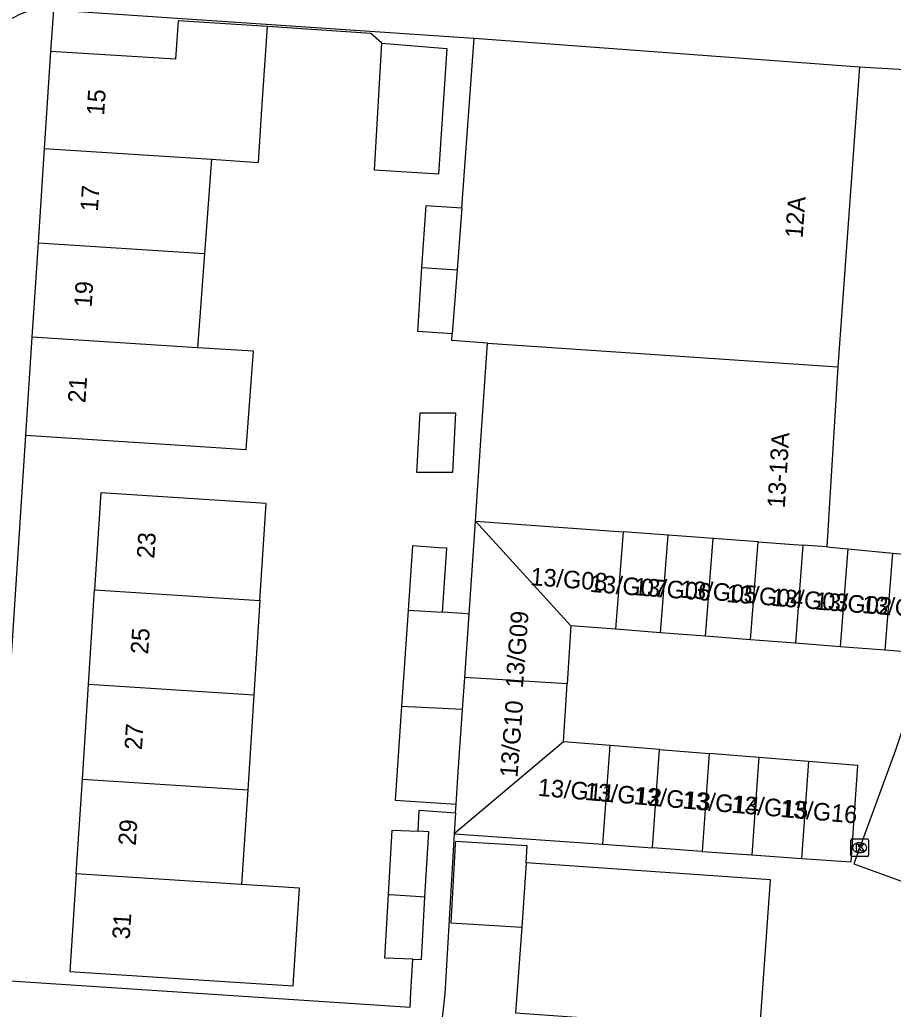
# Model space of a CAD drawing. Extents: x 160356 to 161355, y 381727 to 382845.
# Drawn here: x 160572.4 to 160622.2, y 382168.2 to 382224.6 of the extents above; entities that cross this region are included whole.
import ezdxf

# ---------------------------------------------------------------- set-up
doc = ezdxf.new("R2010")
doc.units = 0
for name, color, linetype in [('IMGEO_Kolk', 7, 'Continuous'), ('IMGEO_Muur', 7, 'Continuous'), ('IMGEO_Pand', 7, 'Continuous'), ('IMGEO_Pand_nummerreeks', 7, 'Continuous'), ('IMGEO_Rijbaan_lokaal_open', 7, 'Continuous'), ('IMGEO_Voetpad_open', 7, 'Continuous')]:
    doc.layers.add(name, color=color, linetype=linetype)

msp = doc.modelspace()

# ---------------------------------------------------------------- linework, layer by layer
at = {"layer": 'IMGEO_Kolk'}
for p, q in [((160619.77, 382176.998), (160619.77, 382177.85)), ((160619.845, 382177.924), (160620.697, 382177.924)), ((160620.258, 382177.704), (160620.283, 382177.704)), ((160620.771, 382177.85), (160620.771, 382176.998)), ((160620.697, 382176.924), (160619.845, 382176.924)), ((160620.281, 382177.144), (160620.256, 382177.144))]:
    msp.add_line(p, q, dxfattribs=at)
for points in [[(160619.77, 382176.998), (160619.77, 382177.85)], [(160619.845, 382177.924), (160620.697, 382177.924)], [(160620.091, 382177.624), (160620.214, 382177.624), (160620.214, 382177.473), (160620.344, 382177.624), (160620.508, 382177.624), (160620.362, 382177.473), (160620.515, 382177.224), (160620.363, 382177.224), (160620.278, 382177.388), (160620.214, 382177.321), (160620.214, 382177.224), (160620.091, 382177.224), (160620.091, 382177.624)], [(160620.771, 382177.85), (160620.771, 382176.998)], [(160620.697, 382176.924), (160619.845, 382176.924)]]:
    msp.add_lwpolyline(points, dxfattribs=at)
for centre, start, end in [((160619.847, 382177.848), 91.552, 178.448), ((160619.847, 382177.848), 91.552, 178.448), ((160620.695, 382177.848), 1.552, 88.448), ((160620.695, 382177.848), 1.552, 88.448), ((160619.847, 382177), 181.552, 268.448), ((160619.847, 382177), 181.552, 268.448), ((160620.695, 382177), 271.552, 358.448), ((160620.695, 382177), 271.552, 358.448)]:
    msp.add_arc(centre, 0.0765, start, end, dxfattribs=at)
for centre, major_axis, ratio, start_param, end_param in [((160620.257, 382177.424), (-0.387, 0.002), 0.722429, 4.712389, 7.853982), ((160620.282, 382177.424), (-0.39, 0.002), 0.717154, 1.570796, 4.712389)]:
    msp.add_ellipse(centre, major_axis=major_axis, ratio=ratio, start_param=start_param, end_param=end_param, dxfattribs=at)
at = {"layer": 'IMGEO_Muur'}
msp.add_lwpolyline([(160593.062, 382223.233), (160592.435, 382223.786), (160586.548, 382224.183)], dxfattribs=at)
at = {"layer": 'IMGEO_Pand'}
for points in [[(160583.35, 382216.629), (160586.024, 382216.454), (160586.21, 382219.195), (160586.548, 382224.183), (160581.462, 382224.509), (160581.314, 382222.32), (160574.19, 382222.775)], [(160592.644, 382216.014), (160593.062, 382223.233), (160596.757, 382222.942), (160596.275, 382215.777), (160592.644, 382216.014)], [(160597.604, 382213.868), (160598.324, 382223.525)], [(160598.324, 382223.525), (160620.253, 382221.901)], [(160574.19, 382222.775), (160573.829, 382217.237)], [(160620.253, 382221.901), (160619.027, 382204.801)], [(160573.829, 382217.237), (160573.479, 382211.868)], [(160573.829, 382217.237), (160583.35, 382216.629)], [(160583.35, 382216.629), (160582.958, 382211.262)], [(160595.343, 382210.47), (160595.58, 382214.004), (160597.604, 382213.868)], [(160597.604, 382213.868), (160597.341, 382210.342)], [(160573.479, 382211.868), (160573.129, 382206.49)], [(160573.479, 382211.868), (160582.958, 382211.262)], [(160582.958, 382211.262), (160582.695, 382207.663), (160582.565, 382205.893)], [(160597.069, 382206.696), (160595.098, 382206.829), (160595.343, 382210.47)], [(160595.343, 382210.47), (160597.341, 382210.342)], [(160597.341, 382210.342), (160597.069, 382206.696)], [(160573.129, 382206.49), (160572.766, 382200.922)], [(160582.565, 382205.893), (160573.129, 382206.49)], [(160599.082, 382206.166), (160597.04, 382206.306), (160597.069, 382206.696)], [(160598.389, 382196.022), (160598.741, 382201.178), (160599.082, 382206.166)], [(160599.082, 382206.166), (160619.027, 382204.801)], [(160572.766, 382200.922), (160577.756, 382200.599), (160582.157, 382200.314), (160585.332, 382200.108), (160585.741, 382205.692), (160582.565, 382205.893)], [(160619.027, 382204.801), (160618.395, 382194.564)], [(160595.058, 382198.801), (160595.234, 382202.194), (160596.91, 382202.194), (160597.253, 382202.194), (160597.077, 382198.801), (160596.91, 382198.801), (160595.058, 382198.801)], [(160586.11, 382191.501), (160586.465, 382197.018), (160582.039, 382197.306), (160577.049, 382197.63), (160576.693, 382192.107)], [(160598.028, 382190.734), (160598.389, 382196.022)], [(160598.389, 382196.022), (160606.802, 382195.409)], [(160598.389, 382196.022), (160603.812, 382190.064)], [(160606.802, 382195.409), (160606.371, 382189.865)], [(160609.363, 382195.222), (160606.802, 382195.409)], [(160608.931, 382189.666), (160609.363, 382195.222)], [(160611.923, 382195.036), (160609.363, 382195.222)], [(160611.49, 382189.467), (160611.923, 382195.036)], [(160614.483, 382194.849), (160611.923, 382195.036)], [(160596.519, 382190.831), (160596.766, 382194.479), (160596.3, 382194.511), (160594.805, 382194.613), (160594.557, 382190.958)], [(160614.049, 382189.268), (160614.483, 382194.849)], [(160614.483, 382194.849), (160617.043, 382194.663)], [(160617.043, 382194.663), (160616.608, 382189.069)], [(160618.395, 382194.564), (160617.043, 382194.663)], [(160618.395, 382194.564), (160619.601, 382194.449)], [(160619.601, 382194.449), (160619.168, 382188.87)], [(160619.601, 382194.449), (160622.157, 382194.206)], [(160622.157, 382194.206), (160624.675, 382193.967), (160624.286, 382188.472), (160621.727, 382188.671)], [(160621.727, 382188.671), (160622.157, 382194.206)], [(160576.346, 382186.714), (160576.693, 382192.107)], [(160576.693, 382192.107), (160586.11, 382191.501)], [(160586.11, 382191.501), (160585.762, 382186.108)], [(160594.557, 382190.958), (160594.186, 382185.471)], [(160594.557, 382190.958), (160596.519, 382190.831)], [(160598.028, 382190.734), (160597.672, 382190.757), (160596.519, 382190.831)], [(160597.78, 382187.112), (160598.028, 382190.734)], [(160603.812, 382190.064), (160603.612, 382186.758)], [(160606.371, 382189.865), (160603.812, 382190.064)], [(160608.931, 382189.666), (160606.371, 382189.865)], [(160611.49, 382189.467), (160608.931, 382189.666)], [(160614.049, 382189.268), (160611.49, 382189.467)], [(160616.608, 382189.069), (160614.049, 382189.268)], [(160619.168, 382188.87), (160616.608, 382189.069)], [(160621.727, 382188.671), (160619.168, 382188.87)], [(160597.655, 382185.291), (160597.78, 382187.112)], [(160603.612, 382186.758), (160597.78, 382187.112)], [(160576, 382181.329), (160576.346, 382186.714)], [(160585.762, 382186.108), (160576.346, 382186.714)], [(160603.411, 382183.453), (160603.612, 382186.758)], [(160585.762, 382186.108), (160585.416, 382180.724)], [(160594.186, 382185.471), (160593.825, 382180.128), (160597.288, 382179.913)], [(160597.655, 382185.291), (160594.186, 382185.471)], [(160597.288, 382179.913), (160597.412, 382181.734), (160597.655, 382185.291)], [(160603.411, 382183.453), (160597.172, 382178.224)], [(160606.052, 382183.241), (160603.411, 382183.453)], [(160605.652, 382177.62), (160606.052, 382183.241)], [(160608.877, 382183.014), (160606.052, 382183.241)], [(160608.478, 382177.419), (160608.877, 382183.014)], [(160608.877, 382183.014), (160611.702, 382182.787)], [(160611.702, 382182.787), (160611.305, 382177.218)], [(160614.526, 382182.56), (160611.702, 382182.787)], [(160614.526, 382182.56), (160614.132, 382177.016)], [(160617.351, 382182.333), (160614.526, 382182.56)], [(160616.958, 382176.815), (160619.785, 382176.614), (160620.176, 382182.106), (160617.351, 382182.333)], [(160617.351, 382182.333), (160616.958, 382176.815)], [(160575.652, 382175.937), (160576, 382181.329)], [(160576, 382181.329), (160585.416, 382180.724)], [(160585.416, 382180.724), (160585.069, 382175.331)], [(160597.254, 382179.42), (160597.288, 382179.913)], [(160597.254, 382179.42), (160597.172, 382178.224)], [(160593.443, 382174.757), (160593.653, 382178.422), (160595.126, 382178.361)], [(160595.515, 382174.631), (160595.728, 382178.336), (160595.126, 382178.361)], [(160597.172, 382178.224), (160605.652, 382177.62)], [(160601.281, 382176.574), (160601.332, 382177.53), (160597.244, 382177.775), (160597.238, 382177.669), (160597.214, 382177.257), (160596.978, 382173.139), (160601.022, 382172.907)], [(160605.652, 382177.62), (160608.478, 382177.419)], [(160611.305, 382177.218), (160608.478, 382177.419)], [(160611.305, 382177.218), (160614.132, 382177.016)], [(160614.132, 382177.016), (160616.958, 382176.815)], [(160601.022, 382172.907), (160600.676, 382168.021), (160614.579, 382167.037), (160615.184, 382175.591), (160601.281, 382176.574)], [(160601.281, 382176.574), (160601.022, 382172.907)], [(160575.652, 382175.937), (160575.295, 382170.384), (160580.285, 382170.063), (160584.711, 382169.778), (160588.014, 382169.565), (160588.372, 382175.119), (160585.069, 382175.331)], [(160585.069, 382175.331), (160575.652, 382175.937)], [(160594.823, 382171.077), (160593.235, 382171.144), (160593.443, 382174.757)], [(160593.443, 382174.757), (160593.507, 382174.753), (160594.972, 382174.664), (160595.515, 382174.631)], [(160594.823, 382171.077), (160595.31, 382171.056), (160595.515, 382174.631)]]:
    msp.add_lwpolyline(points, dxfattribs=at)
at = {"layer": 'IMGEO_Rijbaan_lokaal_open'}
for points in [[(160574.354, 382225.146), (160598.291, 382223.527), (160598.324, 382223.525)], [(160620.253, 382221.901), (160626.057, 382221.56), (160635.558, 382221.001), (160629.938, 382204.897), (160629.671, 382204.116), (160626.275, 382194.168), (160624.387, 382188.463), (160623.792, 382187.389), (160622.316, 382182.98), (160619.935, 382176.513), (160624.54, 382174.828)]]:
    msp.add_lwpolyline(points, dxfattribs=at)
msp.add_arc((160573.896, 382221.438), 3.729, 87.7041, 168.5199, dxfattribs=at)
at = {"layer": 'IMGEO_Voetpad_open'}
for points in [[(160574.354, 382225.146), (160574.19, 382222.775)], [(160572.766, 382200.922), (160570.733, 382169.923)], [(160595.126, 382178.361), (160595.176, 382179.562), (160597.254, 382179.42)], [(160597.172, 382178.224), (160596.653, 382169.099), (160596.417, 382167.081), (160585.894, 382138.53), (160584.28, 382139.124), (160585.048, 382141.122)], [(160570.733, 382169.923), (160594.668, 382168.353), (160594.717, 382169.209), (160594.823, 382171.077)]]:
    msp.add_lwpolyline(points, dxfattribs=at)

# ---------------------------------------------------------------- texts
at = {"layer": 'IMGEO_Pand_nummerreeks'}
for s, rotation, p in [('15', 86.2717, (160577.238, 382219.097)), ('17', 86.2717, (160576.882, 382213.634)), ('12A', 85.7321, (160617.018, 382212.107)), ('19', 86.2717, (160576.526, 382208.17)), ('21', 86.2703, (160576.171, 382202.729)), ('13-13A', 86.4672, (160616.005, 382196.748)), ('23', 86.3166, (160580.094, 382193.87)), ('13/G08', 355.619, (160601.492, 382192.381)), ('13/G07', 355.619, (160604.876, 382191.995)), ('13/G06', 355.619, (160607.392, 382191.811)), ('13/G05', 355.619, (160610.018, 382191.671)), ('13/G04', 355.619, (160612.65, 382191.415)), ('13/G03', 355.619, (160615.214, 382191.203)), ('13/G02', 355.619, (160617.692, 382190.992)), ('13/G01', 355.619, (160620.381, 382190.794)), ('13/G09', 85.6171, (160601.088, 382186.494)), ('25', 86.3166, (160579.743, 382188.421)), ('13/G10', 85.6171, (160600.778, 382181.395)), ('27', 86.3166, (160579.392, 382182.972)), ('13/G11', 355.0263, (160601.914, 382180.383)), ('13/G12', 355.0263, (160604.581, 382180.151)), ('13/G13', 355.0263, (160607.371, 382179.908)), ('13/G14', 355.0263, (160610.154, 382179.666)), ('13/G15', 355.0263, (160612.938, 382179.424)), ('13/G16', 355.0263, (160615.721, 382179.182)), ('29', 86.3166, (160579.041, 382177.522)), ('31', 86.3161, (160578.696, 382172.185))]:
    msp.add_text(s, height=1, rotation=rotation, dxfattribs=at).set_placement(p)

doc.saveas('drawing.dxf')
